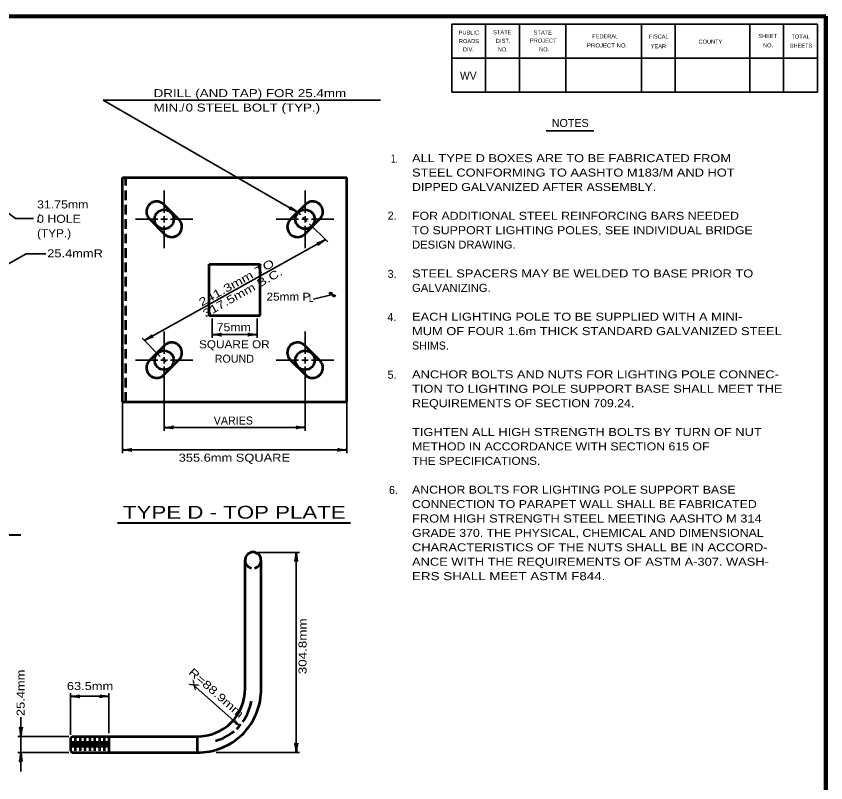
# Model space of a CAD drawing. Extents: x -35 to 821, y -23 to 522.
# Drawn here: x 511 to 814.4, y 228 to 515.2 of the extents above; entities that cross this region are included whole.
import ezdxf
from ezdxf.enums import TextEntityAlignment as Align

# ---------------------------------------------------------------- set-up
doc = ezdxf.new("R2010")
doc.units = 0
doc.header["$LTSCALE"] = 1.2
doc.linetypes.add('MEDIUM_DASHED', pattern=[4.5, 3, -1.5])
doc.layers.add('1', color=7, linetype='Continuous', lineweight=35)
doc.layers.add('61', color=7, linetype='Continuous', lineweight=35)

msp = doc.modelspace()

# ---------------------------------------------------------------- linework, layer by layer
at = {"layer": '1', "lineweight": 158}
msp.add_line((814.415, -10.947), (814.415, 515.153), dxfattribs=at)
at = {"layer": '1', "lineweight": 13}
msp.add_line((814.415, -10.947), (814.415, 515.153), dxfattribs=at)
at = {"layer": '1'}
for p, q in [((543.583, 483.736), (647.549, 483.736)), ((543.583, 483.736), (616.525, 441.627)), ((709.623, 472.238), (727.487, 472.238)), ((566.448, 441.473), (566.448, 449.873)), ((619.248, 441.473), (619.248, 449.873)), ((616.618, 441.703), (617.551, 440.77)), ((564.048, 439.073), (555.648, 439.073)), ((568.848, 439.073), (577.248, 439.073)), ((616.848, 439.073), (608.448, 439.073)), ((618.4, 439.921), (620.097, 438.224)), ((620.946, 437.376), (627.734, 430.588)), ((621.648, 439.073), (630.048, 439.073)), ((566.448, 436.673), (566.448, 428.273)), ((619.248, 436.673), (619.248, 428.273)), ((559.061, 393.661), (626.885, 431.436)), ((629.487, 410.864), (622.452, 409.181)), ((584.448, 401.873), (584.448, 394.673)), ((601.248, 401.873), (601.248, 394.673)), ((558.212, 394.51), (565, 387.721)), ((566.448, 388.673), (566.448, 397.073)), ((584.448, 395.873), (601.248, 395.873)), ((619.248, 388.673), (619.248, 397.073)), ((564.048, 386.273), (555.648, 386.273)), ((565.848, 386.873), (567.048, 385.673)), ((568.848, 386.273), (577.248, 386.273)), ((616.848, 386.273), (608.448, 386.273)), ((621.648, 386.273), (630.048, 386.273)), ((566.448, 383.873), (566.448, 359.873)), ((619.248, 383.873), (619.248, 359.873)), ((550.848, 370.673), (550.848, 351.473)), ((634.848, 370.673), (634.848, 351.473)), ((566.448, 361.073), (619.248, 361.073)), ((550.848, 352.673), (634.848, 352.673)), ((601.549, 314.295), (617.149, 314.295)), ((615.949, 314.295), (615.949, 239.356)), ((594.689, 249.291), (577.256, 264.63)), ((531.349, 245.956), (531.349, 261.556)), ((545.749, 246.556), (545.749, 261.556)), ((531.349, 260.356), (545.749, 260.356)), ((530.749, 245.356), (511.549, 245.356)), ((530.749, 239.356), (511.549, 239.356)), ((585.949, 239.356), (617.149, 239.356))]:
    msp.add_line(p, q, dxfattribs=at)
at = {"layer": '1', "lineweight": 53}
for p, q in [((550.848, 370.673), (550.848, 454.673)), ((550.848, 454.673), (634.848, 454.673)), ((634.848, 370.673), (634.848, 454.673)), ((566.448, 444.473), (571.848, 439.073)), ((619.248, 444.473), (613.848, 439.073)), ((566.448, 433.673), (561.048, 439.073)), ((619.248, 433.673), (624.648, 439.073)), ((583.248, 403.073), (583.248, 422.273)), ((583.248, 422.273), (602.448, 422.273)), ((602.448, 403.073), (602.448, 422.273)), ((583.248, 403.073), (602.448, 403.073)), ((566.448, 391.673), (561.048, 386.273)), ((619.248, 391.673), (624.648, 386.273)), ((566.448, 380.873), (571.848, 386.273)), ((619.248, 380.873), (613.848, 386.273)), ((550.848, 370.673), (634.848, 370.673)), ((596.749, 263.356), (596.749, 311.356)), ((602.749, 263.356), (602.749, 311.356)), ((531.349, 244.756), (531.949, 245.356)), ((531.349, 244.756), (531.349, 239.956)), ((531.949, 245.356), (578.749, 245.356)), ((532.249, 243.556), (532.249, 241.156)), ((533.149, 244.756), (533.149, 239.956)), ((534.049, 243.556), (534.049, 241.156)), ((534.949, 244.756), (534.949, 239.956)), ((535.849, 243.556), (535.849, 241.156)), ((536.749, 244.756), (536.749, 239.956)), ((537.649, 243.556), (537.649, 241.156)), ((538.549, 244.756), (538.549, 239.956)), ((539.449, 243.556), (539.449, 241.156)), ((540.349, 244.756), (540.349, 239.956)), ((541.249, 243.556), (541.249, 241.156)), ((542.149, 244.756), (542.149, 239.956)), ((543.049, 243.556), (543.049, 241.156)), ((543.949, 244.756), (543.949, 239.956)), ((544.849, 243.556), (544.849, 241.156)), ((545.749, 245.356), (545.749, 239.356)), ((578.749, 245.356), (578.749, 239.356)), ((531.349, 239.956), (531.949, 239.356)), ((531.949, 239.356), (578.749, 239.356))]:
    msp.add_line(p, q, dxfattribs=at)
at = {"layer": '1', "linetype": 'MEDIUM_DASHED', "lineweight": 53}
msp.add_line((552.048, 370.673), (552.048, 454.673), dxfattribs=at)
at = {"layer": '1', "lineweight": 40}
for p, q in [((548.929, 325.309), (636.335, 325.309)), ((421.861, 320.845), (512.69, 320.845))]:
    msp.add_line(p, q, dxfattribs=at)
at = {"layer": '1', "lineweight": 158}
msp.add_lwpolyline([(814.415, 515.153), (22.715, 515.053), (22.815, -10.947)], dxfattribs=at)
at = {"layer": '1'}
for points in [[(495.07, 451.002), (510.694, 439.424), (517.508, 439.424)], [(566.448, 437.873), (566.448, 439.073), (566.448, 440.273)], [(619.248, 437.873), (619.248, 439.073), (619.248, 440.273)], [(565.248, 439.073), (566.448, 439.073), (567.648, 439.073)], [(620.448, 439.073), (619.248, 439.073), (618.048, 439.073)], [(499.368, 417.537), (514.706, 426.187), (522.054, 426.187)], [(565.248, 386.273), (566.448, 386.273), (567.648, 386.273)], [(566.448, 387.473), (566.448, 386.273), (566.448, 385.073)], [(620.448, 386.273), (619.248, 386.273), (618.048, 386.273)], [(619.248, 387.473), (619.248, 386.273), (619.248, 385.073)], [(512.749, 252.556), (512.749, 245.356), (512.749, 239.356), (512.749, 232.156)]]:
    msp.add_lwpolyline(points, dxfattribs=at)
at = {"layer": '1', "lineweight": 53}
for centre in [(566.448, 439.073), (619.248, 439.073), (566.448, 386.273), (619.248, 386.273)]:
    msp.add_circle(centre, 3.6, dxfattribs=at)
for centre, radius, start, end in [((563.621, 441.901), 3.823, 42.29136, 227.70864), ((622.076, 441.901), 3.823, 312.29136, 137.70864), ((569.276, 436.245), 3.823, 222.29136, 47.70864), ((616.421, 436.245), 3.823, 132.29136, 317.70864), ((628.877, 410.781), 0.615, 7.71531, 162.28469), ((630.096, 410.947), 0.615, 187.71531, 342.28469), ((569.276, 389.101), 3.823, 312.29136, 137.70864), ((616.421, 389.101), 3.823, 42.29136, 227.70864), ((563.621, 383.445), 3.823, 132.29136, 317.70864), ((622.076, 383.445), 3.823, 222.29136, 47.70864), ((599.749, 311.356), 3, 281.53696, 258.46304), ((579.08, 263.025), 17.672, 268.92697, 1.07303), ((579.249, 262.856), 23.505, 268.78134, 1.21866), ((580.767, 261.668), 18.628, 324.48804, 350.40705), ((580.767, 261.668), 18.628, 313.39217, 320.77939), ((580.767, 261.668), 18.628, 285.43733, 309.6831)]:
    msp.add_arc(centre, radius, start, end, dxfattribs=at)
at = {"layer": '1', "lineweight": 40}
for centre, major_axis, ratio, start_param, end_param in [((615.487, 442.519), (-1.72, 1.236), 0.07063, 6.2823074, 8.5597026), ((615.225, 441.995), (1.949, -0.909), 0.122415, 0.8963533, 3.1415927), ((625.587, 431.004), (-1.944, -0.841), 0.07063, 6.2823074, 8.5597026), ((625.903, 430.51), (1.781, 1.206), 0.122415, 0.8963533, 3.1415927), ((560.043, 394.588), (-1.781, -1.206), 0.122415, 0.8963533, 3.1415927), ((560.043, 394.588), (-1.781, -1.206), 0.122415, 0.8963533, 3.1415927), ((560.359, 394.094), (1.944, 0.841), 0.07063, 6.2823074, 8.5597026), ((560.359, 394.094), (1.944, 0.841), 0.07063, 6.2823074, 8.5597026), ((585.793, 395.619), (-2.108, 0.211), 0.07063, 3.1407148, 5.41811), ((585.793, 395.619), (-2.108, 0.211), 0.07063, 3.1407148, 5.41811), ((585.758, 396.204), (-2.143, -0.187), 0.122415, 0.8963533, 3.1415927), ((585.758, 396.204), (-2.143, -0.187), 0.122415, 0.8963533, 3.1415927), ((599.939, 395.541), (2.143, 0.187), 0.122415, 0.8963533, 3.1415927), ((599.904, 396.127), (2.108, -0.211), 0.07063, 3.1407148, 5.41811), ((567.758, 361.404), (-2.143, -0.187), 0.122415, 0.8963533, 3.1415927), ((567.758, 361.404), (-2.143, -0.187), 0.122415, 0.8963533, 3.1415927), ((617.904, 361.327), (2.108, -0.211), 0.07063, 3.1407148, 5.41811), ((567.793, 360.819), (-2.108, 0.211), 0.07063, 3.1407148, 5.41811), ((567.793, 360.819), (-2.108, 0.211), 0.07063, 3.1407148, 5.41811), ((617.939, 360.741), (2.143, 0.187), 0.122415, 0.8963533, 3.1415927), ((552.193, 352.419), (-2.108, 0.211), 0.07063, 3.1407148, 5.41811), ((552.158, 353.004), (-2.143, -0.187), 0.122415, 0.8963533, 3.1415927), ((633.539, 352.341), (2.143, 0.187), 0.122415, 0.8963533, 3.1415927), ((633.504, 352.927), (2.108, -0.211), 0.07063, 3.1407148, 5.41811), ((615.695, 312.951), (0.211, 2.108), 0.07063, 3.1407148, 5.41811), ((615.695, 312.951), (0.211, 2.108), 0.07063, 3.1407148, 5.41811), ((616.281, 312.986), (-0.187, 2.143), 0.122415, 0.8963533, 3.1415927), ((616.281, 312.986), (-0.187, 2.143), 0.122415, 0.8963533, 3.1415927), ((532.694, 260.102), (-2.108, 0.211), 0.07063, 3.1407148, 5.41811), ((532.694, 260.102), (-2.108, 0.211), 0.07063, 3.1407148, 5.41811), ((532.659, 260.688), (-2.143, -0.187), 0.122415, 0.8963533, 3.1415927), ((532.659, 260.688), (-2.143, -0.187), 0.122415, 0.8963533, 3.1415927), ((544.44, 260.024), (2.143, 0.187), 0.122415, 0.8963533, 3.1415927), ((544.405, 260.61), (2.108, -0.211), 0.07063, 3.1407148, 5.41811), ((593.847, 250.37), (-1.443, 1.551), 0.07063, 6.2823074, 8.5597026), ((512.418, 246.665), (0.187, -2.143), 0.122415, 0.8963533, 3.1415927), ((512.418, 246.665), (0.187, -2.143), 0.122415, 0.8963533, 3.1415927), ((513.003, 246.701), (-0.211, -2.108), 0.07063, 3.1407148, 5.41811), ((513.003, 246.701), (-0.211, -2.108), 0.07063, 3.1407148, 5.41811), ((593.487, 249.907), (1.733, -1.275), 0.122415, 0.8963533, 3.1415927), ((615.618, 240.665), (0.187, -2.143), 0.122415, 0.8963533, 3.1415927), ((616.203, 240.701), (-0.211, -2.108), 0.07063, 3.1407148, 5.41811), ((512.495, 238.011), (0.211, 2.108), 0.07063, 3.1407148, 5.41811), ((512.495, 238.011), (0.211, 2.108), 0.07063, 3.1407148, 5.41811), ((513.081, 238.047), (-0.187, 2.143), 0.122415, 0.8963533, 3.1415927), ((513.081, 238.047), (-0.187, 2.143), 0.122415, 0.8963533, 3.1415927)]:
    msp.add_ellipse(centre, major_axis=major_axis, ratio=ratio, start_param=start_param, end_param=end_param, dxfattribs=at)
at = {"layer": '61'}
for p, q in [((686.915, 512.153), (686.915, 486.753)), ((699.615, 512.153), (699.615, 486.753)), ((717.015, 512.153), (717.015, 486.753)), ((745.315, 512.153), (745.315, 486.753)), ((758.015, 512.153), (758.015, 486.753)), ((785.915, 512.153), (785.915, 486.753)), ((798.615, 512.153), (798.615, 486.753)), ((811.315, 499.453), (674.215, 499.453))]:
    msp.add_line(p, q, dxfattribs=at)
for points in [[(811.315, 512.153), (674.215, 512.153), (674.215, 486.753)], [(811.315, 512.153), (811.315, 486.753), (674.215, 486.753)]]:
    msp.add_lwpolyline(points, dxfattribs=at)

# ---------------------------------------------------------------- texts
at = {"layer": '1'}
for s, height, width, p in [('WV', 3.048, 0.95, (677.315, 491.353)), ('DRILL (AND TAP) FOR 25.4mm', 3, 1.25, (562.491, 484.82)), ('MIN. 0 STEEL BOLT (TYP.)', 3, 1.25, (562.491, 479.42)), ('1.', 3, 0.65, (651.48, 460.308)), ('ALL TYPE D BOXES ARE TO BE FABRICATED FROM', 3, 1.2, (659.344, 460.474)), ('STEEL CONFORMING TO AASHTO M183/M AND HOT', 3, 1.2, (659.344, 455.074)), ('DIPPED GALVANIZED AFTER ASSEMBLY.', 3, 1.15, (659.344, 449.674)), ('31.75mm', 3, 1.15, (518.815, 443.143)), ('0 HOLE', 3, 1.15, (518.815, 437.743)), ('FOR ADDITIONAL STEEL REINFORCING BARS NEEDED', 3, 1.15, (659.344, 438.874)), ('(TYP.)', 3, 1.1, (518.815, 432.343)), ('TO SUPPORT LIGHTING POLES, SEE INDIVIDUAL BRIDGE', 3, 1.15, (659.344, 433.474)), ('DESIGN DRAWING.', 3, 1.05, (659.344, 428.074)), ('25.4mmR', 3, 1.2, (522.611, 424.808)), ('STEEL SPACERS MAY BE WELDED TO BASE PRIOR TO', 3, 1.2, (659.344, 417.274)), ('GALVANIZING.', 3, 1.05, (659.344, 411.874)), ('25mm P', 3, 1.1, (604.794, 408.586)), ('L', 3, 0.65, (620.711, 408.081)), ('EACH LIGHTING POLE TO BE SUPPLIED WITH A MINI-', 3, 1.2, (659.344, 401.074)), ('75mm', 3, 1.15, (586.113, 397.121)), ('MUM OF FOUR 1.6m THICK STANDARD GALVANIZED STEEL', 3, 1.2, (659.344, 395.674)), ('ANCHOR BOLTS AND NUTS FOR LIGHTING POLE CONNEC-', 3, 1.2, (659.344, 379.474)), ('TION TO LIGHTING POLE SUPPORT BASE SHALL MEET THE', 3, 1.2, (659.344, 374.074)), ('REQUIREMENTS OF SECTION 709.24.', 3, 1.15, (659.344, 368.674)), ('TIGHTEN ALL HIGH STRENGTH BOLTS BY TURN OF NUT', 3, 1.2, (659.344, 357.874)), ('METHOD IN ACCORDANCE WITH SECTION 615 OF', 3, 1.15, (659.344, 352.474)), ('355.6mm SQUARE', 3, 1.2, (571.877, 348.257)), ('THE SPECIFICATIONS.', 3, 1.1, (659.344, 347.074)), ('ANCHOR BOLTS FOR LIGHTING POLE SUPPORT BASE', 3, 1.15, (659.344, 336.274)), ('CONNECTION TO PARAPET WALL SHALL BE FABRICATED', 3, 1.15, (659.344, 330.874)), ('TYPE D - TOP PLATE', 4.8, 1.3, (551.01, 326.917)), ('FROM HIGH STRENGTH STEEL MEETING AASHTO M 314', 3, 1.2, (659.344, 325.474)), ('GRADE 370. THE PHYSICAL, CHEMICAL AND DIMENSIONAL', 3, 1.15, (659.344, 320.074)), ('CHARACTERISTICS OF THE NUTS SHALL BE IN ACCORD-', 3, 1.2, (659.344, 314.674)), ('ANCE WITH THE REQUIREMENTS OF ASTM A-307. WASH-', 3, 1.2, (659.344, 309.274)), ('ERS SHALL MEET ASTM F844.', 3, 1.25, (659.344, 303.874)), ('63.5mm', 3, 1.2, (529.958, 262.71))]:
    msp.add_text(s, height=height, dxfattribs=dict(at, width=width)).set_placement(p)
for s, p in [('/', (572.884, 479.388)), ('NOTES', (711.725, 473.647)), ('/', (518.723, 437.858)), ('2.', (650.218, 438.949)), ('3.', (650.201, 417.132)), ('4.', (650.078, 400.955)), ('SHIMS.', (659.344, 390.274)), ('5.', (650.178, 379.338)), ('VARIES', (585.021, 362.177)), ('6.', (650.703, 336.134))]:
    msp.add_text(s, height=3, dxfattribs=at).set_placement(p)
for s, rotation, width, p in [('241.3mm TO', 29.116, 1.35, (580.454, 406.325)), ('317.5mm B.C.', 29.116, 1.3, (581.983, 402.178)), ('304.8mm', 90, 1.25, (619.797, 268.631)), ('R=88.9mm', 318.655, 1.3, (575.357, 268.985)), ('25.4mm', 90, 1.2, (514.144, 252.956)), ('x', 318.655, 2.05, (575.356, 265.128))]:
    msp.add_text(s, height=3, rotation=rotation, dxfattribs=dict(at, width=width)).set_placement(p)
at = {"layer": '1', "width": 1.1}
msp.add_text('SQUARE OR', height=3, dxfattribs=at).set_placement((592.751, 390.739), align=Align.CENTER)
at = {"layer": '1'}
msp.add_text('ROUND', height=3, dxfattribs=at).set_placement((592.751, 385.339), align=Align.CENTER)
at = {"layer": '61'}
for s, height, rotation, p in [('PUBLIC', 1.525, 0.033, (676.815, 508.253)), ('FEDERAL', 1.523, 0.007, (726.915, 506.853)), ('FISCAL', 1.525, 359.942, (748.115, 506.753)), ('SHEET', 1.525, 0.059, (789.115, 506.953)), ('ROADS', 1.525, 0.124, (676.915, 505.053)), ('DIST.', 1.525, 0.056, (690.815, 505.153)), ('YEAR', 1.523, 0.105, (748.815, 503.153)), ('COUNTY', 1.523, 0.069, (766.715, 504.853)), ('SHEETS', 1.523, 359.959, (800.915, 503.353)), ('DIV.', 1.525, 359.932, (678.415, 501.953))]:
    msp.add_text(s, height=height, rotation=rotation, dxfattribs=at).set_placement(p)
for s, rotation, width, p in [('STATE', 0.059, 1.05, (689.715, 508.353)), ('STATE', 0.059, 1.05, (704.915, 508.253)), ('PROJECT', 359.908, 1.05, (703.515, 505.253)), ('TOTAL', 359.926, 1.05, (801.515, 506.753)), ('PROJECT NO.', 359.922, 1.1, (724.915, 503.453)), ('NO.', 359.852, 0.9, (790.915, 503.453)), ('NO.', 359.852, 0.9, (691.515, 501.953)), ('NO.', 0.225, 0.9, (707.015, 501.953))]:
    msp.add_text(s, height=1.525, rotation=rotation, dxfattribs=dict(at, width=width)).set_placement(p)

doc.saveas('drawing.dxf')
